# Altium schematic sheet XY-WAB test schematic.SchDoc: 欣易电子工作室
size A4
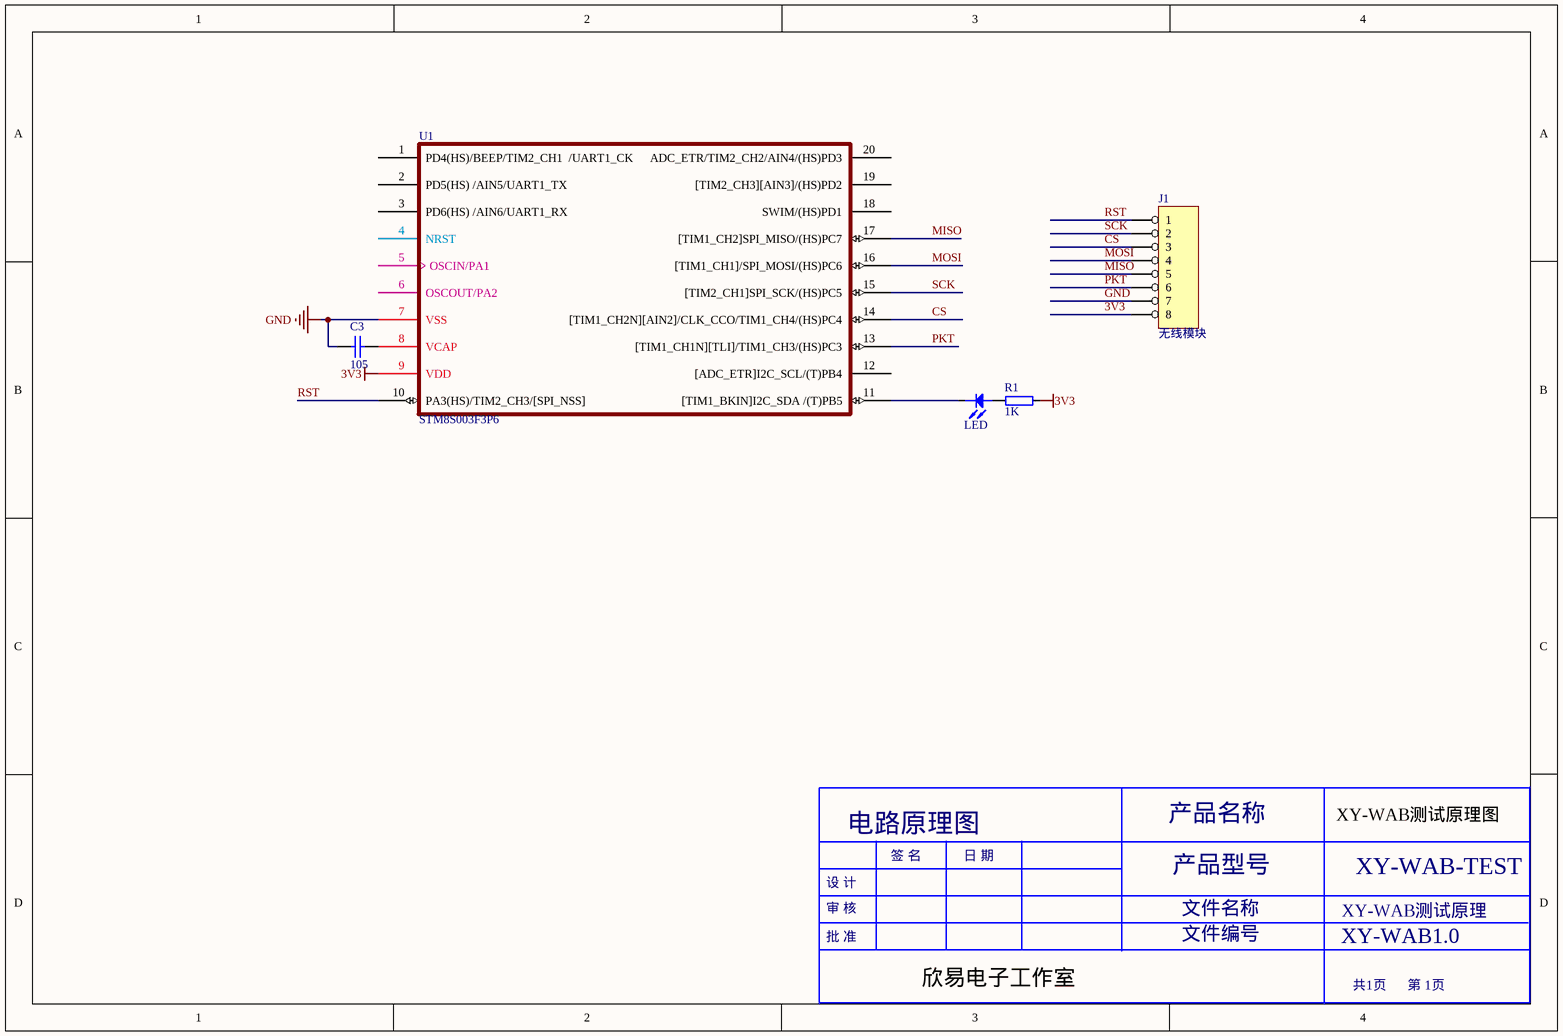
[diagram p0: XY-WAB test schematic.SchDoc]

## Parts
?  LED  [LED]
C3  value 105  [0805C]  (hidden comment: C105)
J1  无线模块
R1  1K  [0805]
U1  STM8S003F3P6  [STM8S]

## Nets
3V3: J1.8 R1.2 U1.9(VDD)
GND: C3.1 J1.7 U1.7(VSS)
CS: J1.3 U1.14([TIM1_CH2N][AIN2]/CLK_CCO/TIM1_CH4/(HS)PC4)
MISO: J1.5 U1.17([TIM1_CH2]SPI_MISO/(HS)PC7)
MOSI: J1.4 U1.16([TIM1_CH1]/SPI_MOSI/(HS)PC6)
PKT: J1.6 U1.13([TIM1_CH1N][TLI]/TIM1_CH3/(HS)PC3)
RST: J1.1 U1.10(PA3(HS)/TIM2_CH3/[SPI_NSS])
SCK: J1.2 U1.15([TIM2_CH1]SPI_SCK/(HS)PC5)
Net?_A: ?.A R1.1
Net?_K: ?.K U1.11([TIM1_BKIN]I2C_SDA_/(T)PB5)
NetC3_2: C3.2 U1.8(VCAP)

Not connected (* = marked no-connect by the designer): U1 1(PD4(HS)/BEEP/TIM2_CH1__/UART1_CK) 2(PD5(HS)_/AIN5/UART1_TX) 3(PD6(HS)_/AIN6/UART1_RX) 4(NRST) 5(OSCIN/PA1) 6(OSCOUT/PA2) 12([ADC_ETR]I2C_SCL/(T)PB4) 18(SWIM/(HS)PD1) 19([TIM2_CH3][AIN3]/(HS)PD2) 20(ADC_ETR/TIM2_CH2/AIN4/(HS)PD3)

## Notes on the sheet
- 电路原理图
- 产品名称
- XY-WAB测试原理图
- 设 计
- 审 核
- 签 名
- 日 期
- 产品型号
- 文件名称
- XY-WAB-TEST
- 批 准
- 文件编号
- XY-WAB1.0
- 欣易电子工作室
- 共1页      第 1页

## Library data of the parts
C3 = Cap: Capacitor
J1 = 8 HEADER: 8 Pin Header
R1 = RES
U1 = STM8S103F2P6: ST 8-bit  Microcontroller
